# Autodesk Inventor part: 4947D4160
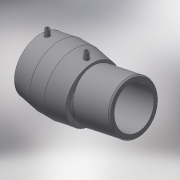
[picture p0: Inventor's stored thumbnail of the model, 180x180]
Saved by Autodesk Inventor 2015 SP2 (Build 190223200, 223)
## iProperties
Created: 2017-06
Part Number: 4947D4160
Material: Generic
Description: PLASSON ADJUSTABLE ELBOW (ONE SIDE) 160
Document SubType Name: Modeling
Designer: KIM
Mass: 55.0731 g
Surface Area: 148.067 cm^2
Volume: 55.0731 cm^3
Density: 1 g/cm^3
Appearance: Default
Author: KIM
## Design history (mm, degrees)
derived "4947D4.ipt"
feature "Solid1::4947D4.ipt"
tag "TaggingFeature1"
body "Solid1"
other parameters: "d0" = 175.875, "d8" = 168 deg, "d11" = 13.33333, "d29" = 114, "d30" = 15, "d31" = 67, "d34" = 5 deg, "d41" = 4, "d42" = 14, "d43" = 0, "d48" = 144, "d55" = 45.525, "d57" = 168 deg, "d62" = 3, "d63" = 0, "d65" = 335, "d67" = 144, "d68" = 135 deg, "d70" = 74, "d71" = 4, "L_" = 335, "A_" = 114, "d_2" = 12, "L_0" = 148, "d54" = 75.875, "d59" = 205.17523
